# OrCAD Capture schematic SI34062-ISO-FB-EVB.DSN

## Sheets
1 PAGE2: size B; title: Si3402 Eval Board - Isolated; rev: 2.0; note: SI34062-ISO-FB-EVB
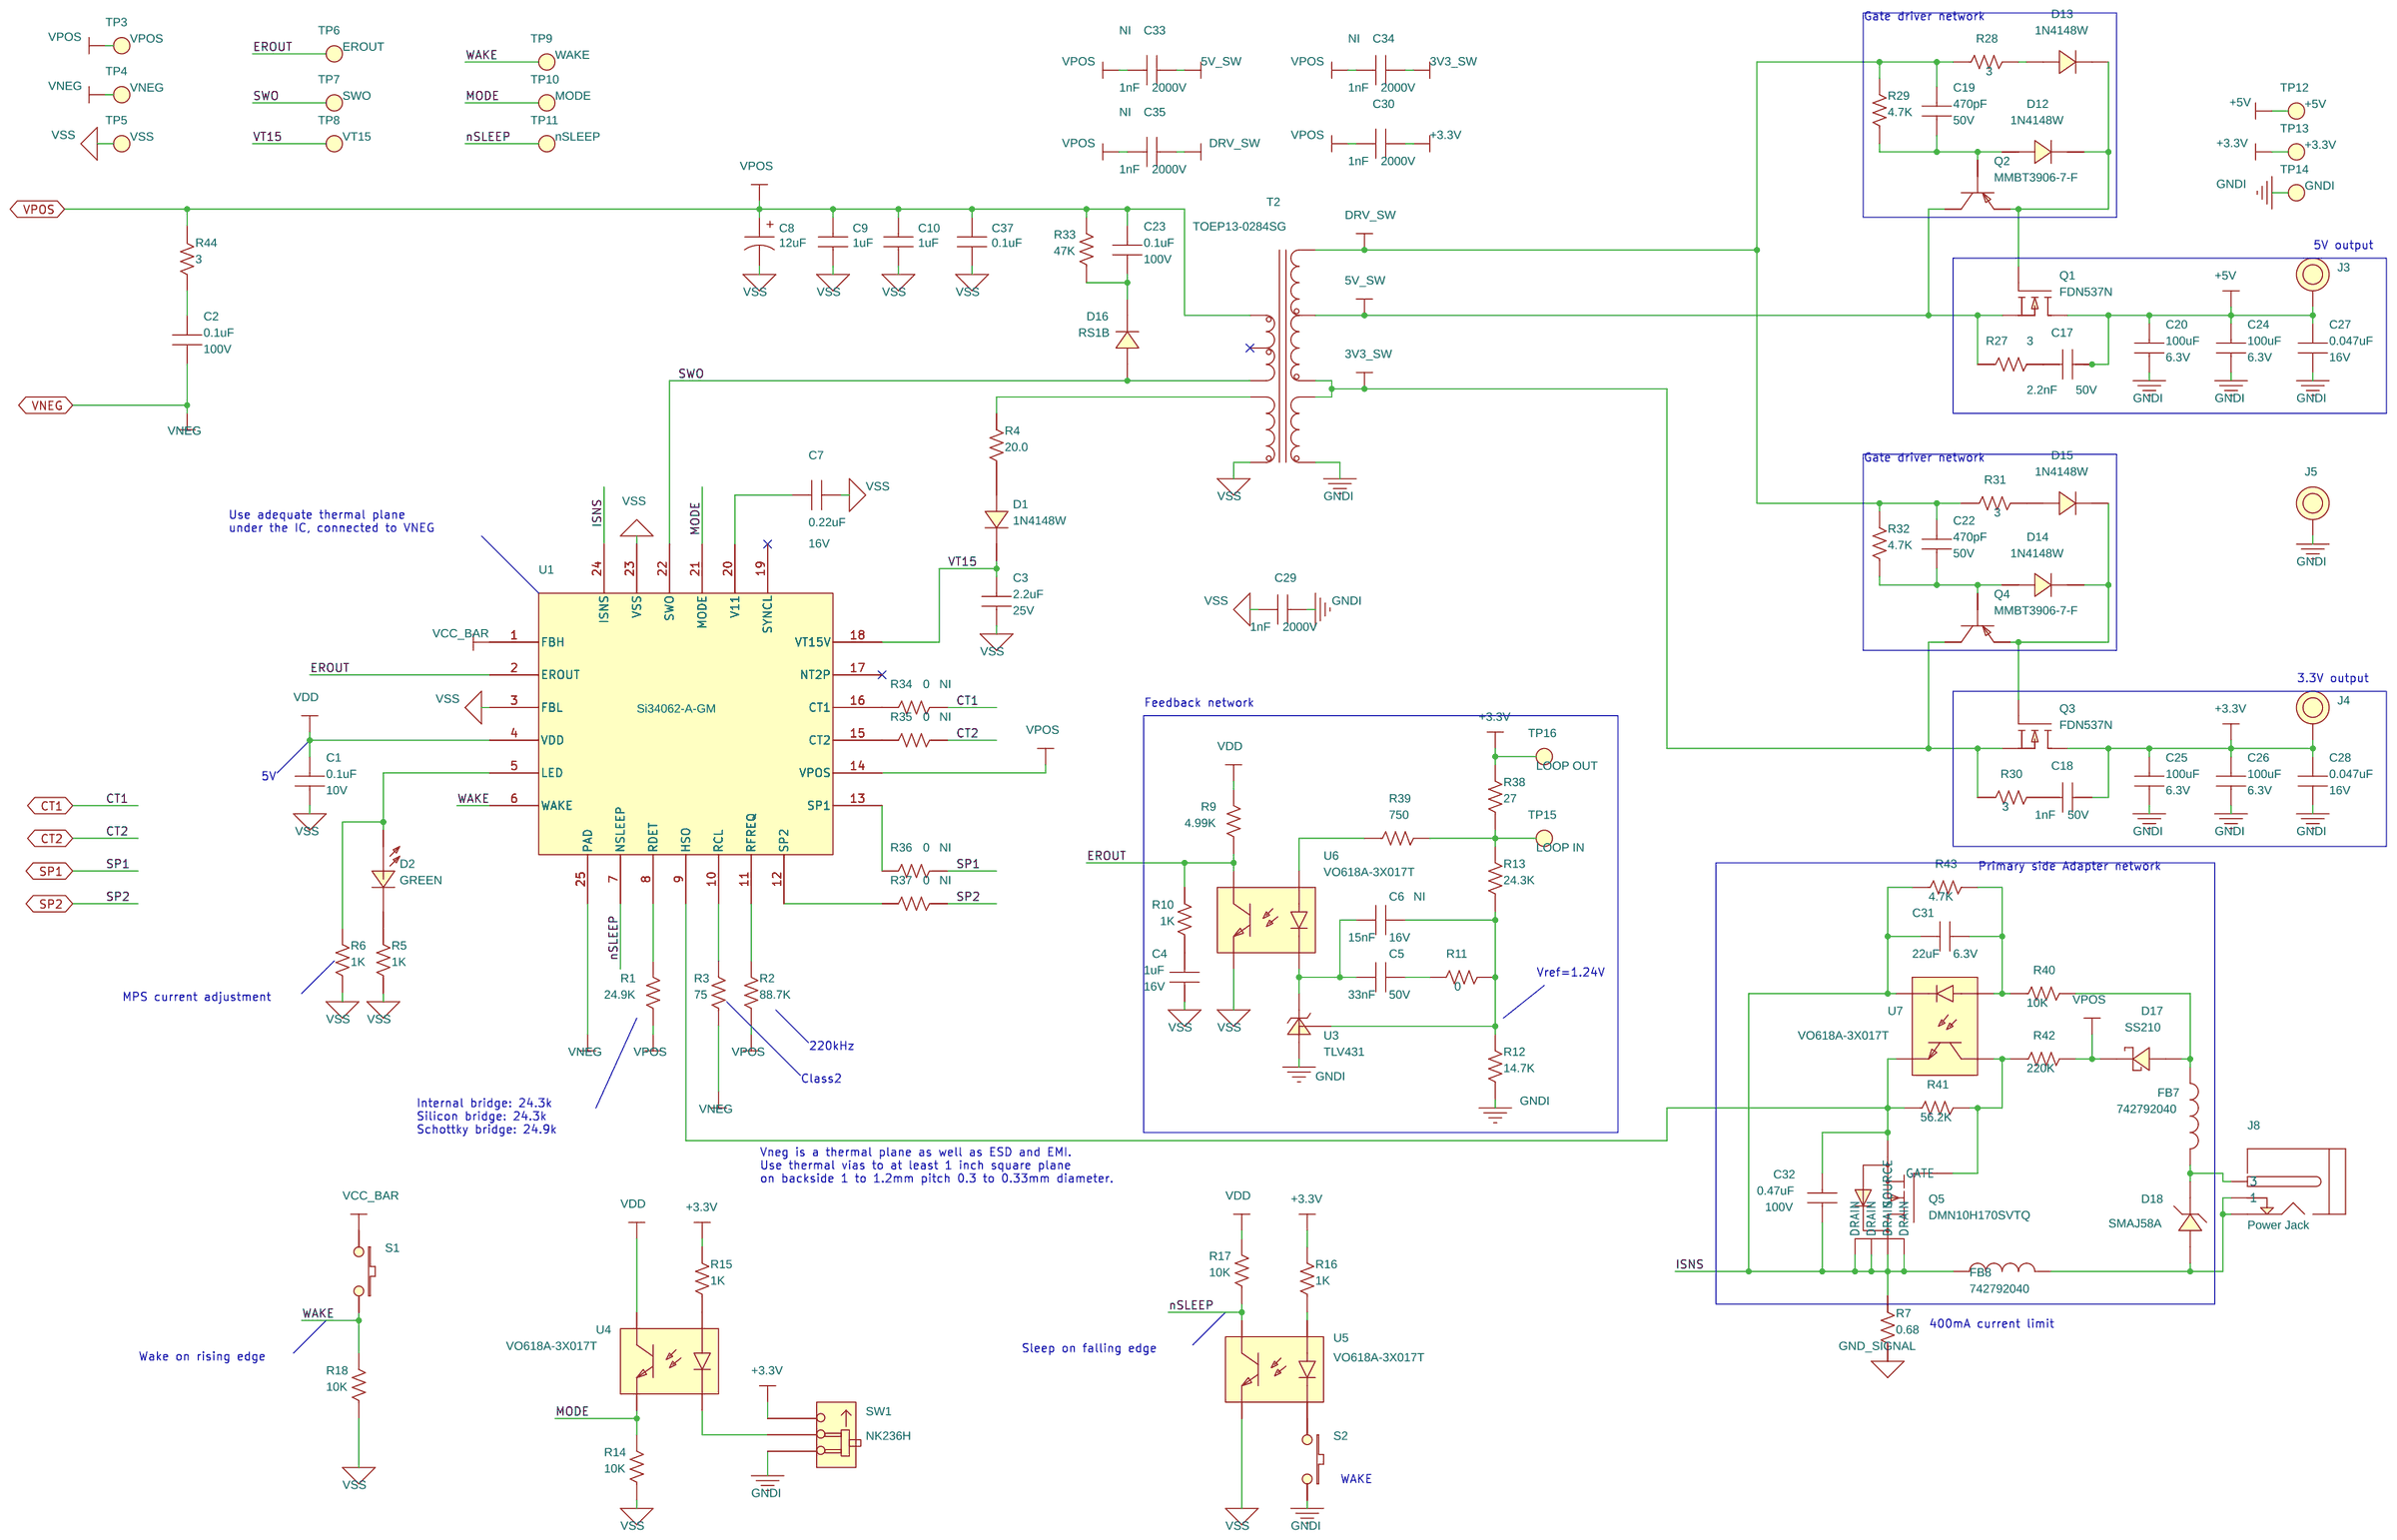
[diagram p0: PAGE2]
2 PAGE1: size B
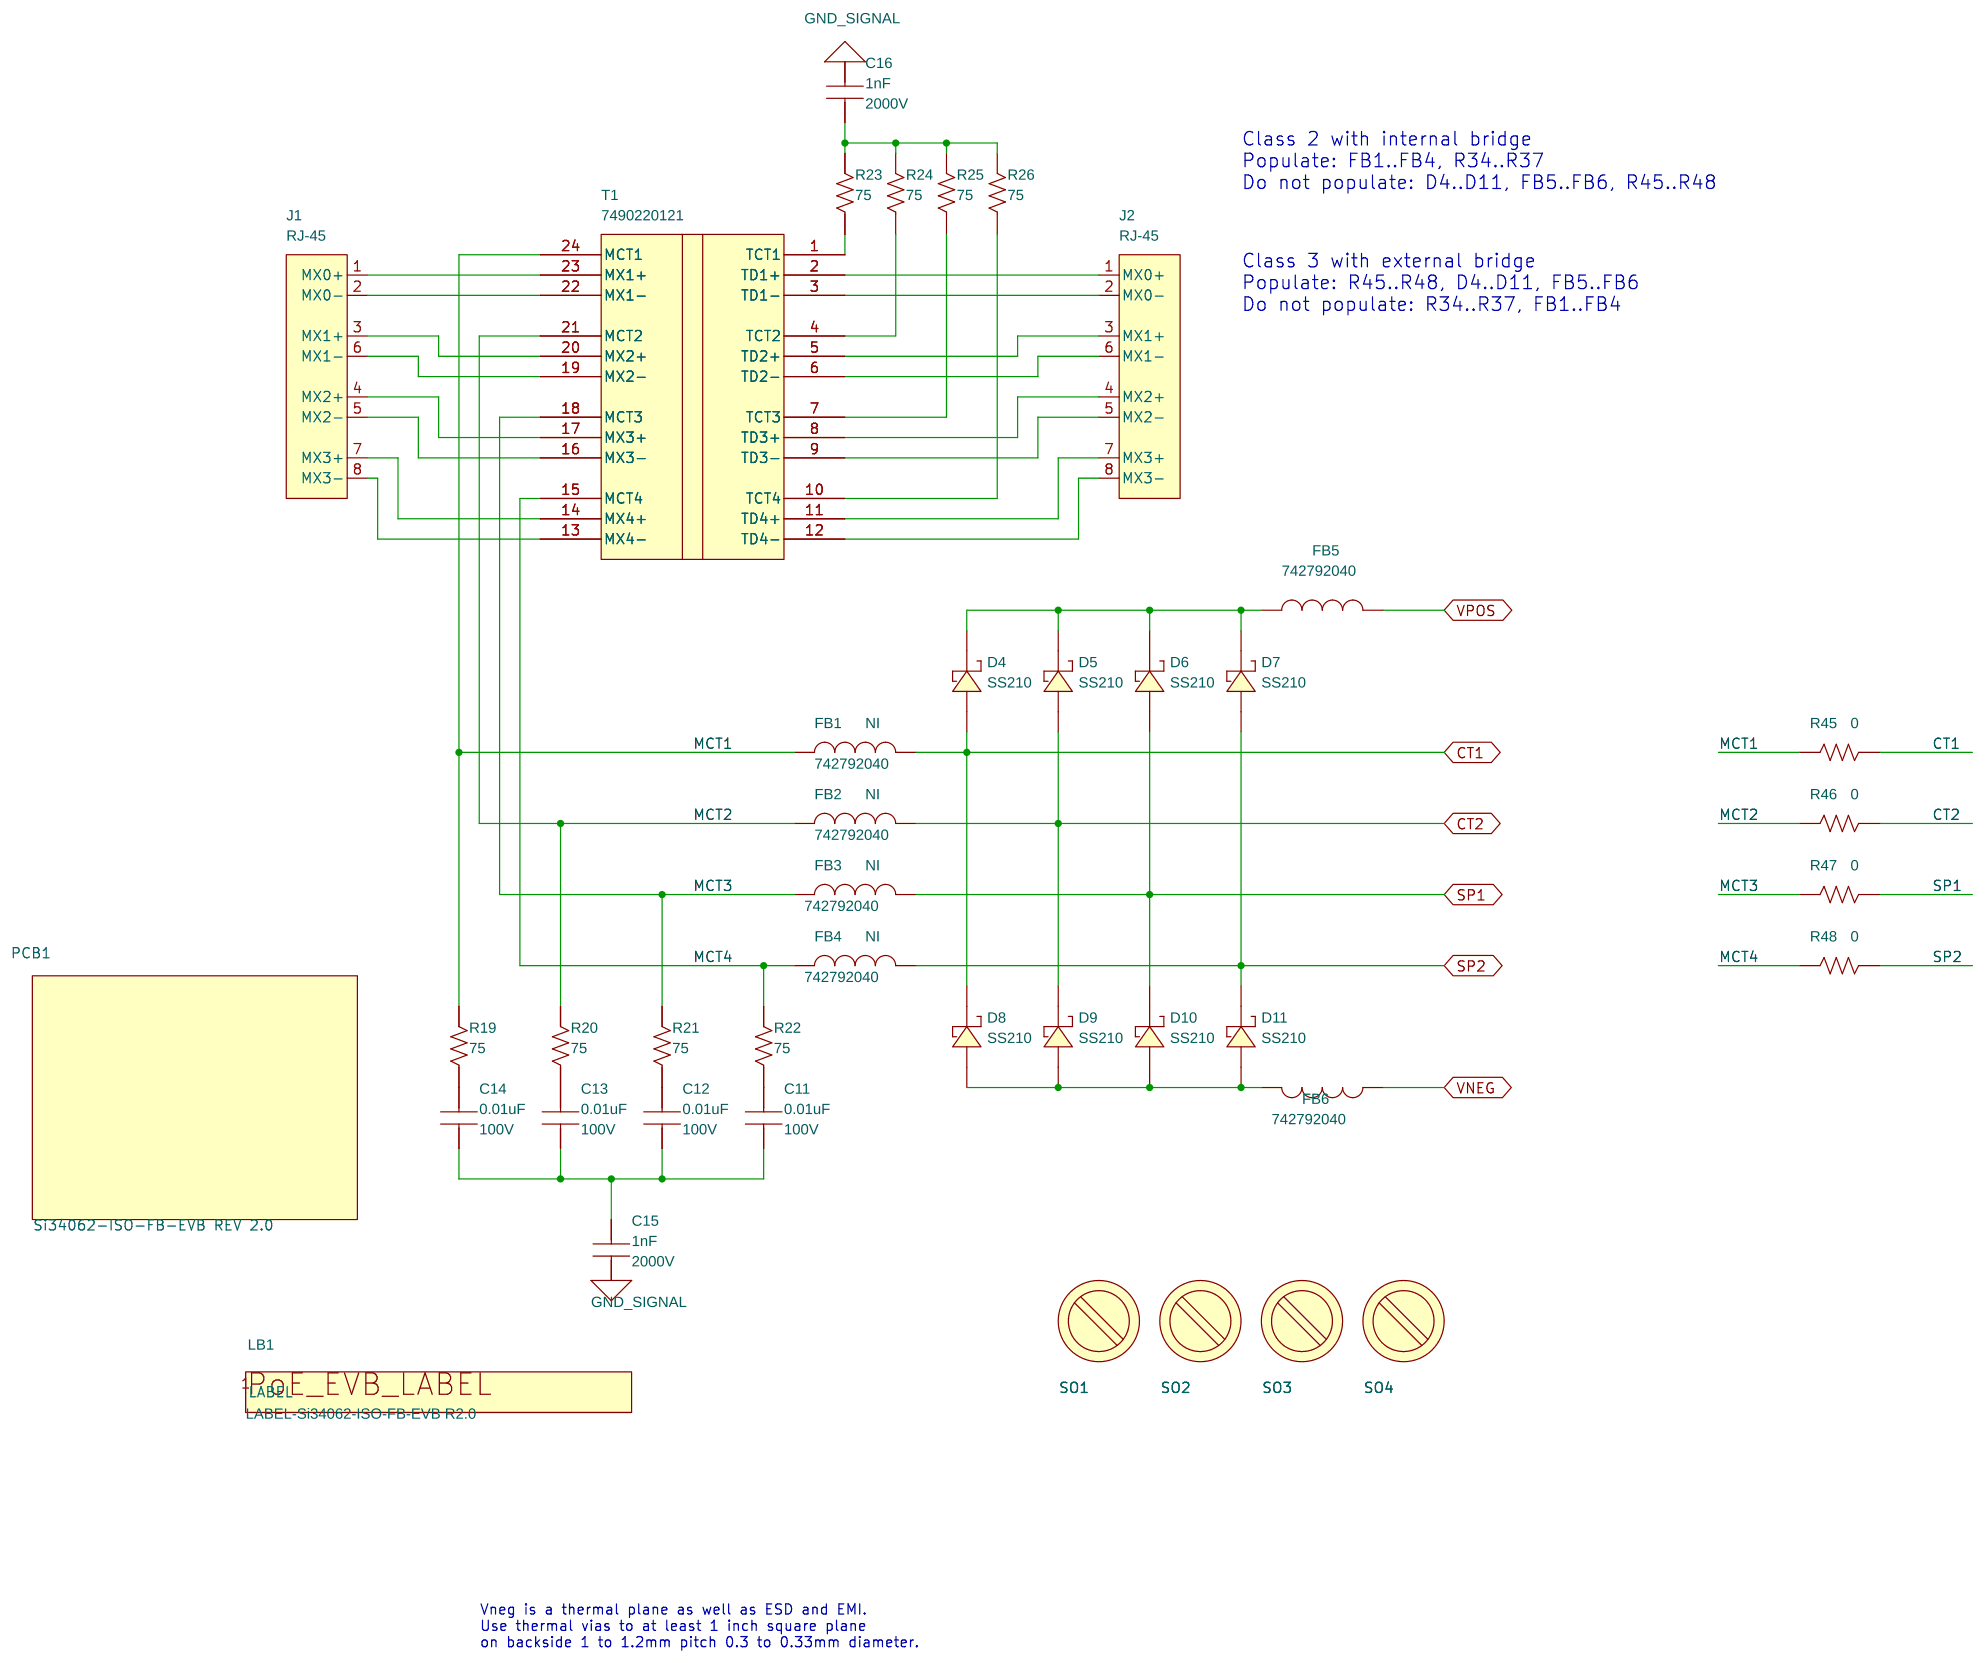
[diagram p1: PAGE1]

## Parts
sheet PAGE1
C11  0.01uF  [C0805]
C12  0.01uF  [C0805]
C13  0.01uF  [C0805]
C14  0.01uF  [C0805]
C15  1nF  [C1206]
C16  1nF  [C1206]
D4  SS210  [DO-214AA]
D5  SS210  [DO-214AA]
D6  SS210  [DO-214AA]
D7  SS210  [DO-214AA]
D8  SS210  [DO-214AA]
D9  SS210  [DO-214AA]
D10  SS210  [DO-214AA]
D11  SS210  [DO-214AA]
FB1  742792040  [L0805]
FB2  742792040  [L0805]
FB3  742792040  [L0805]
FB4  742792040  [L0805]
FB5  742792040  [L0805]
FB6  742792040  [L0805]
J1  RJ-45  [CONN-RJ45-5520252]
J2  RJ-45  [CONN-RJ45-5520252]
LB1  LABEL-Si34062-ISO-FB-EVB R2.0  [PTL-14-477]
MH1  4-40  [MH-125NP]
MH2  4-40  [MH-125NP]
MH3  4-40  [MH-125NP]
MH4  4-40  [MH-125NP]
PCB1  Si34062-ISO-FB-EVB REV 2.0  [N/A]
R19  75  [R0805]
R20  75  [R0805]
R21  75  [R0805]
R22  75  [R0805]
R23  75  [R0805]
R24  75  [R0805]
R25  75  [R0805]
R26  75  [R0805]
R45  0  [R0805]
R46  0  [R0805]
R47  0  [R0805]
R48  0  [R0805]
SO1  STANDOFF
SO2  STANDOFF
SO3  STANDOFF
SO4  STANDOFF
T1  7490220121  [ETH-7490220121]
sheet PAGE2
C1  0.1uF  [C0805]
C2  0.1uF  [C0805]
C3  2.2uF  [C0805]
C4  1uF  [C0805]
C5  33nF  [C0805]
C6  15nF  [C0805]
C7  0.22uF  [C0805]
C8  12uF  [C2.5X6.3MM-RAD]
C9  1uF  [C1210]
C10  1uF  [C1210]
C17  2.2nF  [C0805]
C18  1nF  [C0805]
C19  470pF  [C0805]
C20  100uF  [C1210]
C22  470pF  [C0805]
C23  0.1uF  [C0805]
C24  100uF  [C1210]
C25  100uF  [C1210]
C26  100uF  [C1210]
C27  0.047uF  [C0805]
C28  0.047uF  [C0805]
C29  1nF  [C1206]
C30  1nF  [C1206]
C31  22uF  [C0805]
C32  0.47uF  [C0805]
C33  1nF  [C1206]
C34  1nF  [C1206]
C35  1nF  [C1206]
C37  0.1uF  [C0603]
D1  1N4148W  [SOD-123]
D2  GREEN  [LED-0805-K]
D12  1N4148W  [SOD-123]
D13  1N4148W  [SOD-123]
D14  1N4148W  [SOD-123]
D15  1N4148W  [SOD-123]
D16  RS1B  [DO-214AC]
D17  SS210  [DO-214AA]
D18  SMAJ58A  [DO-214AC]
FB7  742792040  [L0805]
FB8  742792040  [L0805]
J3  BND_POST  [BANANA-JACK]
J4  BND_POST  [BANANA-JACK]
J5  BND_POST  [BANANA-JACK]
J8  Power Jack  [CONN-3-PWR]
Q1  FDN537N  [SOT23-GSD]
Q2  MMBT3906-7-F  [SOT23-BEC]
Q3  FDN537N  [SOT23-GSD]
Q4  MMBT3906-7-F  [SOT23-BEC]
Q5  DMN10H170SVTQ  [SOT6N2.8P0.95_TSOT26]
R1  24.9K  [R0805]
R2  88.7K  [R0805]
R3  75  [R0805]
R4  20.0  [R0805]
R5  1K  [R0805]
R6  1K  [R0805]
R7  0.68  [R1206]
R9  4.99K  [R0805]
R10  1K  [R0805]
R11  0  [R0805]
R12  14.7K  [R0805]
R13  24.3K  [R0805]
R14  10K  [R0805]
R15  1K  [R0805]
R16  1K  [R0805]
R17  10K  [R0805]
R18  10K  [R0805]
R27  3  [R0805]
R28  3  [R0805]
R29  4.7K  [R0805]
R30  3  [R0805]
R31  3  [R0805]
R32  4.7K  [R0805]
R33  47K  [R0805]
R34  0  [R0805]
R35  0  [R0805]
R36  0  [R0805]
R37  0  [R0805]
R38  27  [R0805]
R39  750  [R0805]
R40  10K  [R1206]
R41  56.2K  [R0805]
R42  220K  [R0805]
R43  4.7K  [R0805]
R44  3  [R0805]
S1  MOMENTARY  [SW4N6.5X4.5-PB]
S2  MOMENTARY  [SW4N6.5X4.5-PB]
SW1  SW_SLIDE_2POS  [SW-SPDT-NK236H]
T2  TOEP13-0284SG  [XFMR-TOEP13-0284SG]
TP3  BLACK  [TESTPOINT]
TP4  BLACK  [TESTPOINT]
TP5  BLACK  [TESTPOINT]
TP6  BLACK  [TESTPOINT]
TP7  BLACK  [TESTPOINT]
TP8  BLACK  [TESTPOINT]
TP9  BLACK  [TESTPOINT]
TP10  BLACK  [TESTPOINT]
TP11  BLACK  [TESTPOINT]
TP12  BLACK  [TESTPOINT]
TP13  BLACK  [TESTPOINT]
TP14  BLACK  [TESTPOINT]
TP15  BLACK  [TESTPOINT]
TP16  BLACK  [TESTPOINT]
U1  Si34062-A-GM  [QFN24M5X5P0.65E3.1]
U3  TLV431  [TLV431-DBZ]
U4  VO618A-3X017T  [SO4N10.16P2.54-AKEC]
U5  VO618A-3X017T  [SO4N10.16P2.54-AKEC]
U6  VO618A-3X017T  [SO4N10.16P2.54-AKEC]
U7  VO618A-3X017T  [SO4N10.16P2.54-AKEC]

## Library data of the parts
C11-C14 = CAP_NP: CAP, 0.01uF, 100V, ±10%, X7R, 0805; Manufacturer: Venkel; ManufacturerPN: C0805X7R101-103K; SiLabsPN: C0805X7R101-103K; Tolerance: ±10%; Type: X7R; Voltage: 100V; Datasheet: PID_C.pdf
C15 C16 C29 C30 = CAP_NP: CAP, 1nF, 2000V, ±5%, X7R, 1206; Manufacturer: Kemet; ManufacturerPN: C1206C102JGRACTU; SiLabsPN: C1206C102JGRACTU; Tolerance: ±5%; Type: X7R; Voltage: 2000V; Datasheet: KEM_C1010_X7R_HV_SMD-1102742.pdf
D4-D11 D17 = DIODE_SCHOTTKY: DIO, SINGLE, 100V, 2.0A, SMB; Manufacturer: Taiwan Semi; Rating: 2.0A; Type: Single; Voltage: 100V; Datasheet: TSC_SS22_SERIES.pdf
FB1-FB4 = Ferrite_Bead: FERRITE BEAD, 700 Ohm @150MHZ, 0805; Installed Component: NI; Manufacturer: Wurth; Rating: 2000mA; Type: SMT; Voltage: 700 Ohm @150MHz; Datasheet: 742792040.pdf
FB5-FB8 = Ferrite_Bead: FERRITE BEAD, 700 Ohm @150MHZ, 0805; Manufacturer: Wurth; Rating: 2000mA; Type: SMT; Voltage: 700 Ohm @150MHz; Datasheet: 742792040.pdf
J1 = RJ45_1PORT: CONN, RJ-45, 8P, SIDE ENTRY, PTH; Manufacturer: TE Connectivity AMP Connectors; ManufacturerPN: 5520252-4; SiLabsPN: 5520252-4; Silk: PoE+Data; Type: Receptacle; Datasheet: ENG_CD_5520252_B1.pdf
J2 = RJ45_1PORT: CONN, RJ-45, 8P, SIDE ENTRY, PTH; Manufacturer: TE Connectivity AMP Connectors; ManufacturerPN: 5520252-4; SiLabsPN: 5520252-4; Silk: Data; Type: Receptacle; Datasheet: ENG_CD_5520252_B1.pdf
LB1 = PoE_EVB_Label: LABEL, PDB, POLYIMIDE, WHITE, 1.00 in. X 0.187 in., FONT 2; Manufacturer: Skyworks; Type: POLYIMIDE, WHITE; Datasheet: Brady TLS2200 Label PTL-14-477.pdf
MH1-MH4 = SCREW-Small: HDW, SCREW, 4-40 x 1/4 in. Pan Head, Slotted, Nylon; Manufacturer: Richco Plastic Co; ManufacturerPN: NSS-4-4-01; SiLabsPN: NSS-4-4-01; Type: SCREW; Datasheet: RichcoPlasticCo_Screws.pdf
PCB1 = PCB: PCB, BARE BOARD, Si34062-ISO-FB-EVB REV 2.0; Manufacturer: Skyworks; Type: BARE PCB
R3 R19-R26 = RES: RES, 75 Ohm, 1/10W, ±1%, ThickFilm, 0805; Manufacturer: Venkel; ManufacturerPN: CR0805-10W-75R0F; Rating: 1/10W; SiLabsPN: CR0805-10W-75R0F; Tolerance: ±1%; Type: ThickFilm; Datasheet: PID_CR.pdf
R11 R45-R48 = RES: RES, 0 Ohm, 2A, ThickFilm, 0805; Manufacturer: Venkel; ManufacturerPN: CR0805-10W-000; Rating: 2A; SiLabsPN: CR0805-10W-000; Type: ThickFilm; Datasheet: PID_CR.pdf
SO1-SO4 = STANDOFF: HDW, STANDOFF, 4-40 X 1/2" , Nylon; Manufacturer: SPC Technology; ManufacturerPN: 2397; SiLabsPN: 2397; Datasheet: SPC_Technology_spacers.pdf
T1 = ETH-7490220121: Module, PoE+/PoE++ Magnetics, PULSE XFMR 1CT:1CT TX 1CT:1CT RX, SMD; Manufacturer: Wurth; Rating: 350uH; Type: Ethernet; Datasheet: 7490220121.pdf
C1 = CAP_NP: CAP, 0.1uF, 10V, ±10%, X5R, 0805; Manufacturer: Venkel; ManufacturerPN: C0805X5R100-104KNE; SiLabsPN: C0805X5R100-104K; Tolerance: ±10%; Type: X5R; Voltage: 10V; Datasheet: PID_C.pdf
C2 C23 = CAP_NP: CAP, 0.1uF, 100V, ±10%, X7R, 0805; Manufacturer: Venkel; ManufacturerPN: C0805X7R101-104K; SiLabsPN: C0805X7R101-104K; Tolerance: ±10%; Type: X7R; Voltage: 100V; Datasheet: PID_C.pdf
C3 = CAP_NP: CAP, 2.2uF, 25V, ±20%, X7R, 0805; Manufacturer: Venkel; ManufacturerPN: C0805X7R250-225M; SiLabsPN: C0805X7R250-225M; Tolerance: ±20%; Type: X7R; Voltage: 25V; Datasheet: PID_C.pdf
C4 = CAP_NP: CAP, 1uF, 16V, ±10%, X5R, 0805; Manufacturer: Murata; ManufacturerPN: GRM21BR61C105KA01L; SiLabsPN: C0805X5R160-105K; Tolerance: ±10%; Type: X5R; Voltage: 16V; Datasheet: GRM21BR61C105KA01-01.pdf
C5 = CAP_NP: CAP, 33nF, 50V, ±10%, X7R, 0805; Manufacturer: Venkel; ManufacturerPN: C0805X7R500-333KNE; SiLabsPN: C0805X7R500-333K; Tolerance: ±10%; Type: X7R; Voltage: 50V; Datasheet: PID_C.pdf
C6 = CAP_NP: CAP, 15nF, 16V, ±10%, X7R, 0805; Installed Component: NI; Manufacturer: Venkel; ManufacturerPN: C0805X7R160-153K; SiLabsPN: C0805X7R160-153K; Tolerance: ±10%; Type: X7R; Voltage: 16V; Datasheet: PID_C.pdf
C7 = CAP_NP: CAP, 0.22uF, 16V, ±10%, X7R, 0805; Manufacturer: Venkel; ManufacturerPN: C0805X7R160-224KNE; SiLabsPN: C0805X7R160-224K; Tolerance: ±10%; Type: X7R; Voltage: 16V; Datasheet: PID_C.pdf
C8 = CAP_POL_ALT: CAP, 12uF, 100V, ±20%, AL, 6.3X11.2MM; Manufacturer: Panasonic; ManufacturerPN: EEUFC2A120; SiLabsPN: EEUFC2A120; Tolerance: ±20%; Type: Alum_Elec; Voltage: 100V; Datasheet: ABA0000CE22.pdf
C9 C10 = CAP_NP: CAP, 1uF, 100V, ±10%, X7R, 1210; Manufacturer: Venkel; ManufacturerPN: C1210X7R101-105K; SiLabsPN: C1210X7R101-105K; Tolerance: ±10%; Type: X7R; Voltage: 100V; Datasheet: PID_C.pdf
C17 = CAP_NP: CAP, 2.2nF, 50V, ±10%, C0G, 0805; Manufacturer: Venkel; ManufacturerPN: C0805C0G500-222K; SiLabsPN: C0805C0G500-222K; Tolerance: ±10%; Type: C0G; Voltage: 50V; Datasheet: PID_C.pdf
C18 = CAP_NP: CAP, 1nF, 50V, ±1%, C0G, 0805; Manufacturer: Venkel; ManufacturerPN: C0805C0G500-102F; SiLabsPN: C0805C0G500-102F; Tolerance: ±1%; Type: C0G; Voltage: 50V; Datasheet: PID_C.pdf
C19 C22 = CAP_NP: CAP, 470pF, 50V, ±10%, X7R, 0805; Manufacturer: Venkel; ManufacturerPN: C0805X7R500-471K; SiLabsPN: C0805X7R500-471K; Tolerance: ±10%; Type: X7R; Voltage: 50V; Datasheet: PID_C.pdf
C20 C24-C26 = CAP_NP: CAP, 100uF, 6.3V, ±10%, X5R, 1210; Manufacturer: Venkel; ManufacturerPN: C1210X5R6R3-107K; SiLabsPN: C1210X5R6R3-107K; Tolerance: ±10%; Type: X5R; Voltage: 6.3V; Datasheet: PID_C.pdf
C27 C28 = CAP_NP: CAP, 0.047uF, 16V, ±1%, C0G, 0805; Manufacturer: KEMET; ManufacturerPN: C0805C473F4GAC7800; SiLabsPN: C0805C0G160-473F; Tolerance: ±1%; Type: C0G; Voltage: 16V; Datasheet: KEM_C1003_C0G_SMD.pdf
C31 = CAP_NP: CAP, 22uF, 6.3V, ±20%, X5R, 0805; Manufacturer: Venkel; ManufacturerPN: C0805X5R6R3-226M; SiLabsPN: C0805X5R6R3-226M; Tolerance: ±20%; Type: X5R; Voltage: 6.3V; Datasheet: PID_C.pdf
C32 = CAP_NP: CAP, 0.47uF, 100V, ±10%, X7R, 0805; Manufacturer: Venkel; ManufacturerPN: C0805X7R101-474KNE; SiLabsPN: C0805X7R101-474K; Tolerance: ±10%; Type: X7R; Voltage: 100V; Datasheet: PID_C.pdf
C33-C35 = CAP_NP: CAP, 1nF, 2000V, ±5%, X7R, 1206; Installed Component: NI; Manufacturer: Kemet; ManufacturerPN: C1206C102JGRACTU; SiLabsPN: C1206C102JGRACTU; Tolerance: ±5%; Type: X7R; Voltage: 2000V; Datasheet: KEM_C1010_X7R_HV_SMD-1102742.pdf
C37 = CAP_NP: CAP, 0.1uF, 100V, ±10%, X7R, 0603; Manufacturer: Venkel; ManufacturerPN: C0603X7R101-104K; SiLabsPN: C0603X7R101-104K; Tolerance: ±10%; Type: X7R; Voltage: 100V; Datasheet: PID_C.pdf
D1 D12-D15 = DIODE: DIO, SINGLE, 100V, 300mA, SOD123; Manufacturer: Diodes Inc.; ManufacturerPN: 1N4148W-7-F; Rating: 300mA; SiLabsPN: 1N4148W-7-F; Type: Single; Voltage: 100V; Datasheet: ds30086.pdf
D2 = LED: LED, GREEN, 0805; Manufacturer: LITE_ON INC; ManufacturerPN: LTST-C170GKT; Rating: 30mA; SiLabsPN: LTST-C170GKT; Type: SMT; Voltage: 2.2V; Datasheet: LTST-C170GKT.pdf
D16 = DIODE: DIO, SINGLE, 100V, 1.0A, SMA; Manufacturer: Fairchild; Rating: 1.0A; Type: Single; Voltage: 100V; Datasheet: RS1A.pdf
D18 = DIODE_ZENER: DIO, TVS, UNIDIR, 58V, 400W; Manufacturer: Littelfuse; Rating: 400W; Type: GP; Voltage: 58V; Datasheet: smaj.pdf
J3-J5 = BINDING-POST: CONN, BANANA JACK, Threaded uninsulated; Manufacturer: ABBATRON HH SMITH; ManufacturerPN: 101; Rating: 15A; SiLabsPN: 101; Type: BANANA; Datasheet: SD-101.pdf
J8 = CONN_BARREL_3PIN_ALT: CONN, POWER JACK, RA, 2.1mm, PTH; Manufacturer: Adam Tech; ManufacturerPN: ADC-002-1; Rating: 1A; SiLabsPN: ADC-002-1; Type: BARREL; Datasheet: CatPg200-203.pdf
Q1 Q3 = NFET_3PIN: TRANSISTOR, MOSFET, N-CHNL, 30V, 6.5A, SOT23; Manufacturer: Fairchild; Rating: 6.5A; Type: N-CHNL; Voltage: 30V; Datasheet: FDN537N-1300560.pdf
Q2 Q4 = PNP_3PIN: TRANSISTOR, PNP, 40V, 200mA, SOT23; Manufacturer: Diodes Inc.; Rating: 200mA; Type: PNP; Voltage: 40V; Datasheet: MMBT3906-7-F_Diodes_Inc.pdf
Q5 = NFET_6PIN_DMN10H170SVTQ: TRANSISTOR, MOSFET, NFET, 100V, 2.6A, TSOT26; Manufacturer: Diodes Incorporated; Rating: 2.6A; Type: NFET; Voltage: 100V; Datasheet: DMN10H170SVTQ.pdf
R1 = RES: RES, 24.9K, 1/10W, ±1%, ThickFilm, 0805; Manufacturer: Venkel; ManufacturerPN: CR0805-10W-2492FT; Rating: 1/10W; SiLabsPN: CR0805-10W-2492F; Tolerance: ±1%; Type: ThickFilm; Datasheet: PID_CR.pdf
R2 = RES: RES, 88.7K, 1/8W, ±1%, ThickFilm, 0805; Manufacturer: Vishay; ManufacturerPN: CRCW080588K7FKEA; Rating: 1/8W; SiLabsPN: CR0805-8W-8872F; Tolerance: ±1%; Type: ThickFilm; Datasheet: dcrcwe3-109170.pdf
R4 = RES: RES, 20.0 Ohm, 1/8W, ±1%, ThickFilm, 0805; Manufacturer: Venkel; ManufacturerPN: CR0805-8W-20R0F; Rating: 1/8W; SiLabsPN: CR0805-8W-20R0F; Tolerance: ±1%; Type: ThickFilm; Datasheet: PID_CR.pdf
R5 R6 R10 R15 R16 = RES: RES, 1K, 1/10W, ±1%, ThickFilm, 0805; Manufacturer: Venkel; ManufacturerPN: CR0805-10W-1001F; Rating: 1/10W; SiLabsPN: CR0805-10W-1001F; Tolerance: ±1%; Type: ThickFilm; Datasheet: PID_CR.pdf
R7 = RES: RES, 0.68 Ohm, 1/2W, ±1%, ThickFilm, 1206; Manufacturer: Vishay; ManufacturerPN: RCWE1206R680FKEA; Rating: 1/2W; SiLabsPN: CR1206-2W-R680F; Tolerance: ±1%; Type: ThickFilm; Datasheet: rcwe-244377.pdf
R9 = RES: RES, 4.99K, 1/10W, ±1%, ThickFilm, 0805; Manufacturer: Venkel; ManufacturerPN: CR0805-10W-4991F; Rating: 1/10W; SiLabsPN: CR0805-10W-4991F; Tolerance: ±1%; Type: ThickFilm; Datasheet: PID_CR.pdf
R12 = RES: RES, 14.7K, 1/10W, ±1%, ThickFilm, 0805; Manufacturer: Venkel; ManufacturerPN: CR0805-10W-1472F; Rating: 1/10W; SiLabsPN: CR0805-10W-1472F; Tolerance: ±1%; Type: ThickFilm; Datasheet: PID_CR.pdf
R13 = RES: RES, 24.3K, 1/10W, ±1%, ThickFilm, 0805; Manufacturer: Venkel; ManufacturerPN: CR0805-10W-2432F; Rating: 1/10W; SiLabsPN: CR0805-10W-2432F; Tolerance: ±1%; Type: ThickFilm; Datasheet: PID_CR.pdf
R14 R17 R18 = RES: RES, 10K, 1/8W, ±1%, ThickFilm, 0805; Manufacturer: Venkel; ManufacturerPN: CR0805-8W-1002F; Rating: 1/8W; SiLabsPN: CR0805-8W-1002F; Tolerance: ±1%; Type: ThickFilm; Datasheet: PID_CR.pdf
R27 R28 R30 R31 R44 = RES: RES, 3 Ohm, 1/8W, ±1%, ThickFilm, 0805; Manufacturer: Venkel; ManufacturerPN: CR0805-8W-3R00FT; Rating: 1/8W; SiLabsPN: CR0805-8W-3R00F; Tolerance: ±1%; Type: ThickFilm; Datasheet: PID_CR.pdf
R29 R32 R43 = RES: RES, 4.7K, 1/8W, ±5%, ThickFilm, 0805; Manufacturer: Venkel; ManufacturerPN: CR0805-8W-472J; Rating: 1/8W; SiLabsPN: CR0805-8W-472J; Tolerance: ±5%; Type: ThickFilm; Datasheet: PID_CR.pdf
R33 = RES: RES, 47K, 1/10W, ±5%, ThickFilm, 0805; Manufacturer: Venkel; ManufacturerPN: CR0805-10W-473J; Rating: 1/10W; SiLabsPN: CR0805-10W-473J; Tolerance: ±5%; Type: ThickFilm; Datasheet: PID_CR.pdf
R34-R37 = RES: RES, 0 Ohm, 2A, ThickFilm, 0805; Installed Component: NI; Manufacturer: Venkel; ManufacturerPN: CR0805-10W-000; Rating: 2A; SiLabsPN: CR0805-10W-000; Type: ThickFilm; Datasheet: PID_CR.pdf
R38 = RES: RES, 27 Ohm, 1/10W, ±1%, ThickFilm, 0805; Manufacturer: Venkel; ManufacturerPN: CR0805-10W-27R0F; Rating: 1/10W; SiLabsPN: CR0805-10W-27R0F; Tolerance: ±1%; Type: ThickFilm; Datasheet: PID_CR.pdf
R39 = RES: RES, 750 Ohm, 1/8W, ±1%, ThickFilm, 0805; Manufacturer: Venkel; ManufacturerPN: CR0805-8W-7500FT; Rating: 1/8W; SiLabsPN: CR0805-8W-7500F; Tolerance: ±1%; Type: ThickFilm; Datasheet: PID_CR.pdf
R40 = RES: RES, 10K, 1/4W, ±5%, ThickFilm, 1206; Manufacturer: Venkel; ManufacturerPN: CR1206-4W-103J; Rating: 1/4W; SiLabsPN: CR1206-4W-103J; Tolerance: ±5%; Type: ThickFilm; Datasheet: PID_CR.pdf
R41 = RES: RES, 56.2K, 1/8W, ±1%, ThickFilm, 0805; Manufacturer: Venkel; ManufacturerPN: CR0805-8W-5622FT; Rating: 1/8W; SiLabsPN: CR0805-8W-5622F; Tolerance: ±1%; Type: ThickFilm; Datasheet: PID_CR.pdf
R42 = RES: RES, 220K, 1/8W, ±1%, ThickFilm, 0805; Manufacturer: Venkel; ManufacturerPN: CR0805-8W-2203FT; Rating: 1/8W; SiLabsPN: CR0805-8W-2203F; Tolerance: ±1%; Type: ThickFilm; Datasheet: PID_CR.pdf
S1 S2 = SW_PUSHBUTTON_SHORT: SWITCH, PB, NO, MOMENTARY, TACTILE, LIGHT TOUCH 130GF, 6MM, PTH; Manufacturer: PANASONIC CORP; ManufacturerPN: EVQ-PAD04M; SiLabsPN: EVQ-PAD04M; Type: Tactile; Datasheet: ATK0000CE10.pdf
SW1 = 100MIL_SLIDER_SWITCH: SWITCH, SPDT, SLIDE, ON-ON, 0.1 PITCH, 12V, PTH; Manufacturer: Apem Inc.; ManufacturerPN: NK236H; Rating: 0.5A @ 12VDC; SiLabsPN: NK236H; Type: SLIDE; Datasheet: switch-slide-NK-ENG.pdf
T2 = XFMR_Mentech_TOEP13-0284SG: TRANSFORMER, Flyback, 15W, SMT; Manufacturer: Mentech; Datasheet: TOEP13-0284SG SPEC X1 2018-11-9.pdf
TP3 = TEST_POINT: TESTPOINT, BLACK, 0.050" LOOP, PTH; Manufacturer: Keystone; ManufacturerPN: 5001; SiLabsPN: 5001; Silk: VPOS; Type: LOOP; Datasheet: Keystone_thm_datasheet.pdf
TP4 = TEST_POINT: TESTPOINT, BLACK, 0.050" LOOP, PTH; Manufacturer: Keystone; ManufacturerPN: 5001; SiLabsPN: 5001; Silk: VNEG; Type: LOOP; Datasheet: Keystone_thm_datasheet.pdf
TP5 = TEST_POINT: TESTPOINT, BLACK, 0.050" LOOP, PTH; Manufacturer: Keystone; ManufacturerPN: 5001; SiLabsPN: 5001; Silk: VSS; Type: LOOP; Datasheet: Keystone_thm_datasheet.pdf
TP6 = TEST_POINT: TESTPOINT, BLACK, 0.050" LOOP, PTH; Manufacturer: Keystone; ManufacturerPN: 5001; SiLabsPN: 5001; Silk: EROUT; Type: LOOP; Datasheet: Keystone_thm_datasheet.pdf
TP7 = TEST_POINT: TESTPOINT, BLACK, 0.050" LOOP, PTH; Manufacturer: Keystone; ManufacturerPN: 5001; SiLabsPN: 5001; Silk: SWO; Type: LOOP; Datasheet: Keystone_thm_datasheet.pdf
TP8 = TEST_POINT: TESTPOINT, BLACK, 0.050" LOOP, PTH; Manufacturer: Keystone; ManufacturerPN: 5001; SiLabsPN: 5001; Silk: VT15; Type: LOOP; Datasheet: Keystone_thm_datasheet.pdf
TP9 = TEST_POINT: TESTPOINT, BLACK, 0.050" LOOP, PTH; Manufacturer: Keystone; ManufacturerPN: 5001; SiLabsPN: 5001; Silk: WAKE; Type: LOOP; Datasheet: Keystone_thm_datasheet.pdf
TP10 = TEST_POINT: TESTPOINT, BLACK, 0.050" LOOP, PTH; Manufacturer: Keystone; ManufacturerPN: 5001; SiLabsPN: 5001; Silk: MODE; Type: LOOP; Datasheet: Keystone_thm_datasheet.pdf
TP11 = TEST_POINT: TESTPOINT, BLACK, 0.050" LOOP, PTH; Manufacturer: Keystone; ManufacturerPN: 5001; SiLabsPN: 5001; Silk: nSLEEP; Type: LOOP; Datasheet: Keystone_thm_datasheet.pdf
TP12 = TEST_POINT: TESTPOINT, BLACK, 0.050" LOOP, PTH; Manufacturer: Keystone; ManufacturerPN: 5001; SiLabsPN: 5001; Silk: +5V; Type: LOOP; Datasheet: Keystone_thm_datasheet.pdf
TP13 = TEST_POINT: TESTPOINT, BLACK, 0.050" LOOP, PTH; Manufacturer: Keystone; ManufacturerPN: 5001; SiLabsPN: 5001; Silk: +3.3V; Type: LOOP; Datasheet: Keystone_thm_datasheet.pdf
TP14 = TEST_POINT: TESTPOINT, BLACK, 0.050" LOOP, PTH; Manufacturer: Keystone; ManufacturerPN: 5001; SiLabsPN: 5001; Silk: GNDI; Type: LOOP; Datasheet: Keystone_thm_datasheet.pdf
TP15 = TEST_POINT: TESTPOINT, BLACK, 0.050" LOOP, PTH; Manufacturer: Keystone; ManufacturerPN: 5001; SiLabsPN: 5001; Silk: LOOP IN; Type: LOOP; Datasheet: Keystone_thm_datasheet.pdf
TP16 = TEST_POINT: TESTPOINT, BLACK, 0.050" LOOP, PTH; Manufacturer: Keystone; ManufacturerPN: 5001; SiLabsPN: 5001; Silk: LOOP OUT; Type: LOOP; Datasheet: Keystone_thm_datasheet.pdf
U1 = Si34062: IC, IEEE 802.3-Compliant POE+ PD Interface, QFN24; Manufacturer: Skyworks; Datasheet: si3406x-datasheet.pdf
U3 = SHUNT_REG: IC, ADJ PREC SHUNT REG LV SOT-23 Voltage-Output 1.24 ~ 6V; Manufacturer: TI; ManufacturerPN: TLV431BCDBZR; SiLabsPN: TLV431BCDBZR; Type: SHUNT; Datasheet: tlv431a.pdf
U4-U7 = OPTOCOUPLER: PHOTOCOUPLER, 5300Vrms Isolation, 4-PIN SMD; Manufacturer: Vishay; Datasheet: vo618a-244754.pdf

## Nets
3V3_SW: C34.2 Q3.S(SOURCE) Q4.C(COLLECTOR) R30.1 T2.8 T2.9
5V_SW: C33.2 Q1.S(SOURCE) Q2.C(COLLECTOR) R27.1 T2.7
+3.3V: C18.2 C25.1 C26.1 C28.1 C30.2 J4.1(BP) Q3.D(DRAIN) R15.2 R16.2 R38.2 SW1.3 TP13.1(Point) TP16.1(Point)
+5V: C17.2 C20.1 C24.1 C27.1 J3.1(BP) Q1.D(DRAIN) TP12.1(Point)
GNDI: C20.2 C24.2 C25.2 C26.2 C27.2 C28.2 C29.2 J5.1(BP) R12.1 S2.3 S2.4 SW1.2 T2.10 TP14.1(Point) U3.A(Anode)
VDD: C1.2 R9.2 R17.2 S1.1 S1.2 U1.4(VDD) U4.C(COLLECTOR)
VSS: C1.1 C3.2 C4.2 C7.2 C8.2 C9.2 C10.2 C29.1 C37.2 R5.1 R6.1 R7.1 R14.1 R18.1 T2.3 TP5.1(Point) U1.3(FBL) U1.23(VSS) U5.E(EMITTER) U6.E(EMITTER)
BS_Plane: C15.2 C16.1
CT1: D4.A(ANODE) D8.K(CATHODE) FB1.2 R34.1 R45.1
CT2: D5.A(ANODE) D9.K(CATHODE) FB2.2 R35.1 R46.1
DRV_SW: C19.1 C22.1 C35.2 R28.1 R29.2 R31.1 R32.2 T2.6
EROUT: R9.1 R10.2 TP6.1(Point) U1.2(EROUT) U6.C(COLLECTOR)
ISNS: C31.1 C32.2 FB8.1 Q5.1(DRAIN) Q5.2(DRAIN) Q5.5(DRAIN) Q5.6(DRAIN) R7.2 R43.1 U1.24(ISNS) U7.K(CATHODE)
LABEL: LB1.1(LABEL)
MCT1: FB1.1 R19.2 R45.2 T1.24(MCT1)
MCT2: FB2.1 R20.2 R46.2 T1.21(MCT2)
MCT3: FB3.1 R21.2 R47.2 T1.18(MCT3)
MCT4: FB4.1 R22.2 R48.2 T1.15(MCT4)
MODE: R14.2 TP10.1(Point) U1.21(MODE) U4.E(EMITTER)
nSLEEP: R17.1 TP11.1(Point) U1.7(NSLEEP) U5.C(COLLECTOR)
SP1: D6.A(ANODE) D10.K(CATHODE) FB3.2 R36.1 R47.1
SP2: D7.A(ANODE) D11.K(CATHODE) FB4.2 R37.1 R48.1
SWO: D16.A(ANODE) T2.1 TP7.1(Point) U1.22(SWO)
VNEG: C2.2 FB6.1 R3.1 TP4.1(Point) U1.25(PAD)
VPOS: C8.1 C9.1 C10.1 C23.1 C30.1 C33.1 C34.1 C35.1 C37.1 D17.K(CATHODE) FB5.2 R1.1 R2.1 R33.2 R42.2 R44.1 T2.2 TP3.1(Point) U1.1(FBH) U1.14(VPOS)
VT15: C3.1 D1.K(CATHODE) TP8.1(Point) U1.18(VT15V)
WAKE: R18.2 S1.3 S1.4 TP9.1(Point) U1.6(WAKE)
N1634874: D8.A(ANODE) D9.A(ANODE) D10.A(ANODE) D11.A(ANODE) FB6.2
N1635390: D4.K(CATHODE) D5.K(CATHODE) D6.K(CATHODE) D7.K(CATHODE) FB5.1
N1635730: J1.3(MX1+) T1.20(MX2+)
N1635734: J1.2(MX0-) T1.22(MX1-)
N1635738: J1.1(MX0+) T1.23(MX1+)
N1635750: J1.5(MX2-) T1.16(MX3-)
N1635754: J1.4(MX2+) T1.17(MX3+)
N1635774: J1.8(MX3-) T1.13(MX4-)
N1635778: J1.7(MX3+) T1.14(MX4+)
N1635790: J1.6(MX1-) T1.19(MX2-)
N1635810: J2.1(MX0+) T1.2(TD1+)
N1635814: J2.3(MX1+) T1.5(TD2+)
N1635822: J2.2(MX0-) T1.3(TD1-)
N1635826: J2.6(MX1-) T1.6(TD2-)
N1635842: J2.5(MX2-) T1.9(TD3-)
N1635846: J2.4(MX2+) T1.8(TD3+)
N1635858: J2.7(MX3+) T1.11(TD4+)
N1635874: J2.8(MX3-) T1.12(TD4-)
N1635936: C11.2 C12.2 C13.2 C14.2 C15.1
N1636036: R23.1 T1.1(TCT1)
N1636040: R26.1 T1.10(TCT4)
N1636044: R25.1 T1.7(TCT3)
N1636052: R24.1 T1.4(TCT2)
N1636070: C16.2 R23.2 R24.2 R25.2 R26.2
N1651762: Q5.3(GATE) R41.2 R42.1 U7.C(COLLECTOR)
N1651766: C32.1 Q5.4(SOURCE) R41.1 U1.9(HSO) U7.E(EMITTER)
N1651866: C31.2 R40.1 R43.2 U7.A(ANODE)
N1652078: R37.2 U1.12(SP2)
N1652370: D2.A(ANODE) R6.2 U1.5(LED)
N1652390: D17.A(ANODE) FB7.1 R40.2
N1652508: C5.1 C6.1 U3.K(Cathode) U6.K(CATHODE)
N1652560: C6.2 R11.1 R12.2 R13.1 U3.REF(VREF)
N1652564: C5.2 R11.2
N1652666: R39.1 U6.A(ANODE)
N1652748: C7.1 U1.20(V11)
N1652922: SW1.1 U4.K(CATHODE)
N1653090: R13.2 R38.1 R39.2 TP15.1(Point)
N1653468: C19.2 D12.A(ANODE) Q2.B(BASE) R29.1
N1653516: D12.K(CATHODE) D13.K(CATHODE) Q1.G(GATE) Q2.E(EMMITER)
N1653706: C22.2 D14.A(ANODE) Q4.B(BASE) R32.1
N1653750: D14.K(CATHODE) D15.K(CATHODE) Q3.G(GATE) Q4.E(EMMITER)
N1654050: R36.2 U1.13(SP1)
N1654062: R16.1 U5.A(ANODE)
N1654098: D18.A(ANODE) FB8.2 J8.2 J8.3(1)
N1654102: D18.K(CATHODE) FB7.2 J8.1(3)
N1654540: R4.2 T2.4
N1654712: D13.A(ANODE) R28.2
N1655220: R1.2 U1.8(RDET)
N1655248: R2.2 U1.11(RFREQ)
N1655332: R3.2 U1.10(RCL)
N1655438: C23.2 D16.K(CATHODE) R33.1
N1679613: C2.1 R44.2
N1684691: C11.1 R22.1
N1684693: C12.1 R21.1
N1684695: C14.1 R19.1
N1684696: C13.1 R20.1
N1685267: R15.1 U4.A(ANODE)
N1685268: D2.K(CATHODE) R5.2
N1685269: R34.2 U1.16(CT1)
N1685271: C4.1 R10.1
N1685272: D15.A(ANODE) R31.2
N1685273: C18.1 R30.2
N1685274: D1.A(ANODE) R4.1
N1685275: R35.2 U1.15(CT2)
N1685276: C17.1 R27.2
N1685277: S2.1 S2.2 U5.K(CATHODE)

Not connected (* = marked no-connect by the designer): T2 5*; U1 17(NT2P)* 19(SYNCL)*

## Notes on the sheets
sheet 1
- Gate driver network
- 5V output
- Gate driver network
- Use adequate thermal plane
  under the IC, connected to VNEG
- 3.3V output
- Feedback network
- 5V
- Primary side Adapter network
- Vref=1.24V
- MPS current adjustment
- 220kHz
- Class2
- Internal bridge: 24.3k
  Silicon bridge: 24.3k
  Schottky bridge: 24.9k
- Vneg is a thermal plane as well as ESD and EMI.
  Use thermal vias to at least 1 inch square plane
  on backside 1 to 1.2mm pitch 0.3 to 0.33mm diameter.
- 400mA current limit
- Wake on rising edge
- Sleep on falling edge
- WAKE
sheet 2
- Class 2 with internal bridge
  Populate: FB1..FB4, R34..R37
  Do not populate: D4..D11, FB5..FB6, R45..R48
- Class 3 with external bridge
  Populate: R45..R48, D4..D11, FB5..FB6
  Do not populate: R34..R37, FB1..FB4
- Vneg is a thermal plane as well as ESD and EMI.
  Use thermal vias to at least 1 inch square plane
  on backside 1 to 1.2mm pitch 0.3 to 0.33mm diameter.
